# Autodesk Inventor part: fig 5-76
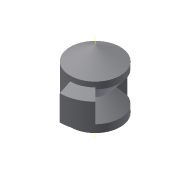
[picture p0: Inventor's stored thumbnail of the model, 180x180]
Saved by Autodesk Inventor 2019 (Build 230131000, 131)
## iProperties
Created: 2004-05
Part Number: fig 5-76
Document SubType Name: Modeling
Designer: CADCIM Technologies
Manufacturer: Standard
Standards Organization: Custom
Density: 1 g/cm^3
Material: Generic
Appearance: Default
Author: CADCIM Technologies
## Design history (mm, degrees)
sketch "Sketch1"
  geometry: L1 (0, -21.51)-(0, 21.51); L2 (0, 21.51)-(-14.639, 13.059); L3 (-14.639, 13.059)-(-14.639, -13.059); L4 (-14.639, -13.059)-(0, -21.51); 2 further points
  constraints: 8 end point, 1 coincident, 1 equal length, 1 midpoint, 1 parallel, 1 vertical, 1 other
  dimensions: "d3" = 120 deg angle of L4 L3
revolve "Revolution1" sketch "Sketch1" stored, may be unused: angle "d0" = 90 deg
workaxis "Work Axis1"
sketch "Sketch2"
  geometry: L1 (-15.658, 10.423)-(-7.144, 0); L2 (-7.144, 0)-(-15.658, -9.738); L3 (-15.658, -9.738)-(-15.658, 10.423); L4 (0, -25.812)-(0, 34.416) reference
  constraints: 6 end point, 1 vertical
revolve "Revolution2" sketch "Sketch2" stored, may be unused: angle "d4" = 140 deg
sketch "Sketch3"
  geometry: L1 (-14.955, 9.983)-(-20.736, 7.191); L2 (-20.736, 7.191)-(-20.736, -7.686); L3 (-20.736, -7.686)-(-15, -10.57); L4 (0, -25.812)-(0, 34.416) reference
  constraints: 6 end point, 1 equal length, 1 vertical
revolve "Revolution4" sketch "Sketch3" stored, may be unused: angle "d9" = 45 deg
body "Solid1"
other parameters: "d10" = 45 deg
